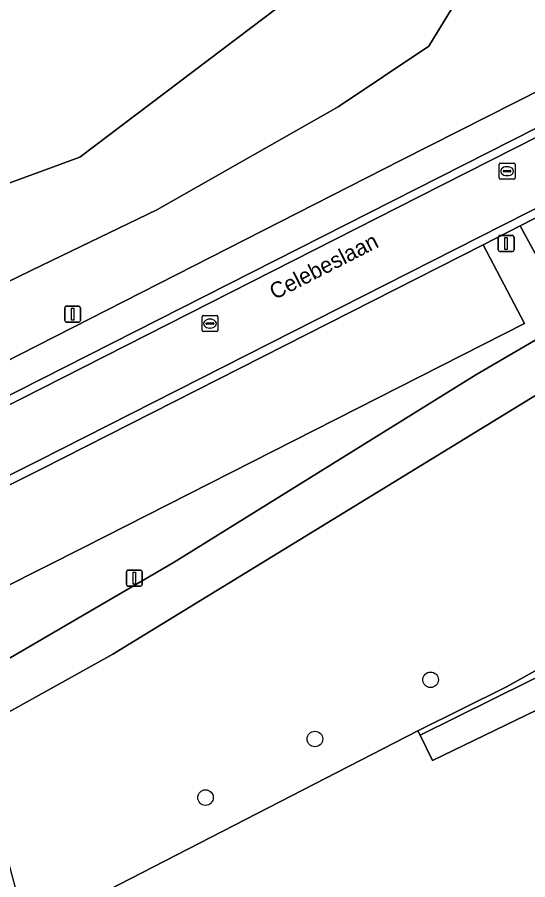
# Model space of a CAD drawing. Extents: x 162879 to 165540, y 384011 to 385181.
# Drawn here: x 163405.9 to 163438, y 384370.1 to 384424.3 of the extents above; entities that cross this region are included whole.
import ezdxf

# ---------------------------------------------------------------- set-up
doc = ezdxf.new("R2010")
doc.units = 0
for name, color, linetype in [('IMGEO_Boom', 7, 'Continuous'), ('IMGEO_Erf', 7, 'Continuous'), ('IMGEO_Grasland_agrarisch', 7, 'Continuous'), ('IMGEO_Groenvoorziening', 7, 'Continuous'), ('IMGEO_Lichtmast', 7, 'Continuous'), ('IMGEO_Loofbos', 7, 'Continuous'), ('IMGEO_Meer_plas_ven_vijver', 7, 'Continuous'), ('IMGEO_Oever', 7, 'Continuous'), ('IMGEO_Openbare_ruimte_label', 7, 'Continuous'), ('IMGEO_Parkeervlak_open', 7, 'Continuous'), ('IMGEO_Rijbaan_lokaal_gesloten', 7, 'Continuous'), ('IMGEO_Rijbaan_lokaal_open', 7, 'Continuous'), ('IMGEO_Rioolput', 7, 'Continuous'), ('IMGEO_Voetpad_open', 7, 'Continuous'), ('IMGEO_Waterloop', 7, 'Continuous')]:
    doc.layers.add(name, color=color, linetype=linetype)

msp = doc.modelspace()

# ---------------------------------------------------------------- linework, layer by layer
at = {"layer": 'IMGEO_Boom'}
for centre in [(163431.908, 384382.643), (163424.634, 384378.918), (163417.752, 384375.234)]:
    msp.add_circle(centre, 0.489, dxfattribs=at)
at = {"layer": 'IMGEO_Erf'}
msp.add_lwpolyline([(163450.353, 384386.442), (163432.033, 384377.572), (163431.249, 384379.155), (163431.11, 384379.435), (163406.542, 384366.796)], dxfattribs=at)
at = {"layer": 'IMGEO_Grasland_agrarisch'}
for points in [[(163373.344, 384387.242), (163392.671, 384396.393), (163404.998, 384402.561), (163430.054, 384415.32), (163455.223, 384428.073)], [(163434.64, 384427.147), (163431.791, 384422.504), (163426.093, 384418.689), (163414.696, 384412.208), (163407.482, 384408.714), (163393.529, 384401.958), (163385.976, 384398.831), (163382.825, 384397.527), (163377.571, 384391.429), (163376.372, 384390.807), (163372.445, 384393.316)]]:
    msp.add_lwpolyline(points, dxfattribs=at)
at = {"layer": 'IMGEO_Groenvoorziening'}
msp.add_lwpolyline([(163434.759, 384401.832), (163440.643, 384405.264), (163440.732, 384405.317), (163437.546, 384411.196), (163435.219, 384410.006), (163437.817, 384405.06), (163410.112, 384390.976), (163399.869, 384385.833), (163399.777, 384385.786), (163401.73, 384381.953), (163402.925, 384382.559), (163415.788, 384390.039)], close=True, dxfattribs=at)
at = {"layer": 'IMGEO_Lichtmast'}
for p, q in [((163436.167, 384409.679), (163436.167, 384410.479)), ((163436.167, 384410.479), (163436.167, 384409.679)), ((163436.267, 384410.579), (163437.057, 384410.579)), ((163437.057, 384410.579), (163436.267, 384410.579)), ((163437.157, 384410.479), (163437.157, 384409.679)), ((163437.157, 384409.679), (163437.157, 384410.479)), ((163437.057, 384409.579), (163436.267, 384409.579)), ((163436.267, 384409.579), (163437.057, 384409.579)), ((163408.893, 384405.238), (163408.893, 384406.038)), ((163408.893, 384406.038), (163408.893, 384405.238)), ((163408.993, 384406.138), (163409.783, 384406.138)), ((163409.783, 384406.138), (163408.993, 384406.138)), ((163409.883, 384406.038), (163409.883, 384405.238)), ((163409.883, 384405.238), (163409.883, 384406.038)), ((163409.783, 384405.138), (163408.993, 384405.138)), ((163408.993, 384405.138), (163409.783, 384405.138)), ((163412.774, 384388.634), (163412.774, 384389.434)), ((163412.774, 384389.434), (163412.774, 384388.634)), ((163412.874, 384389.534), (163413.664, 384389.534)), ((163413.664, 384389.534), (163412.874, 384389.534)), ((163413.764, 384389.434), (163413.764, 384388.634)), ((163413.764, 384388.634), (163413.764, 384389.434)), ((163413.664, 384388.534), (163412.874, 384388.534)), ((163412.874, 384388.534), (163413.664, 384388.534))]:
    msp.add_line(p, q, dxfattribs=at)
for points in [[(163436.587, 384410.454), (163436.737, 384410.454), (163436.737, 384409.704), (163436.587, 384409.704), (163436.587, 384410.454)], [(163409.313, 384406.013), (163409.463, 384406.013), (163409.463, 384405.263), (163409.313, 384405.263), (163409.313, 384406.013)], [(163413.194, 384389.409), (163413.344, 384389.409), (163413.344, 384388.659), (163413.194, 384388.659), (163413.194, 384389.409)]]:
    msp.add_lwpolyline(points, dxfattribs=at)
for centre, start, end in [((163436.267, 384410.479), 90, 180), ((163436.267, 384410.479), 90, 180), ((163437.057, 384410.479), 0, 90), ((163437.057, 384410.479), 360, 90), ((163436.267, 384409.679), 180, 270), ((163436.267, 384409.679), 180, 270), ((163437.057, 384409.679), 270, 0), ((163437.057, 384409.679), 270, 0), ((163408.993, 384406.038), 90, 180), ((163408.993, 384406.038), 90, 180), ((163409.783, 384406.038), 0, 90), ((163409.783, 384406.038), 360, 90), ((163408.993, 384405.238), 180, 270), ((163408.993, 384405.238), 180, 270), ((163409.783, 384405.238), 270, 0), ((163409.783, 384405.238), 270, 0), ((163412.874, 384389.434), 90, 180), ((163412.874, 384389.434), 90, 180), ((163413.664, 384389.434), 0, 90), ((163413.664, 384389.434), 360, 90), ((163412.874, 384388.634), 180, 270), ((163412.874, 384388.634), 180, 270), ((163413.664, 384388.634), 270, 0), ((163413.664, 384388.634), 270, 0)]:
    msp.add_arc(centre, 0.1, start, end, dxfattribs=at)
at = {"layer": 'IMGEO_Loofbos'}
msp.add_lwpolyline([(163431.11, 384379.435), (163436.679, 384382.204), (163448.933, 384389.034), (163448.876, 384389.139), (163449.105, 384389.273), (163449.263, 384389.349), (163442.041, 384402.685), (163411.931, 384384.253), (163403.114, 384379.365), (163406.542, 384366.796)], close=True, dxfattribs=at)
at = {"layer": 'IMGEO_Meer_plas_ven_vijver'}
msp.add_lwpolyline([(163372.906, 384400.903), (163375.7, 384391.868), (163375.807, 384391.922), (163376.372, 384390.807), (163377.571, 384391.429), (163377.047, 384392.564), (163377.156, 384392.615), (163379.868, 384400.144), (163382.737, 384402.812), (163393.452, 384408.404), (163395.885, 384410.398), (163409.847, 384415.517), (163423.24, 384425.652)], dxfattribs=at)
at = {"layer": 'IMGEO_Oever'}
msp.add_lwpolyline([(163423.24, 384425.652), (163409.847, 384415.517), (163395.885, 384410.398), (163393.452, 384408.404), (163382.737, 384402.812), (163379.868, 384400.144), (163377.156, 384392.615), (163377.047, 384392.564), (163377.571, 384391.429), (163382.825, 384397.527), (163385.976, 384398.831), (163393.529, 384401.958), (163407.482, 384408.714), (163414.696, 384412.208), (163426.093, 384418.689), (163431.791, 384422.504), (163434.64, 384427.147)], dxfattribs=at)
msp.add_lwpolyline([(163449.415, 384388.155), (163448.933, 384389.034), (163436.679, 384382.204), (163431.11, 384379.435), (163431.249, 384379.155)], close=True, dxfattribs=at)
at = {"layer": 'IMGEO_Parkeervlak_open'}
for points in [[(163435.219, 384410.006), (163407.444, 384395.905), (163398.254, 384391.345), (163396.481, 384390.495)], [(163397.784, 384390.073), (163399.869, 384385.833), (163410.112, 384390.976), (163437.817, 384405.06), (163435.219, 384410.006)]]:
    msp.add_lwpolyline(points, dxfattribs=at)
at = {"layer": 'IMGEO_Rijbaan_lokaal_gesloten'}
msp.add_lwpolyline([(163397.114, 384391.355), (163398.126, 384391.858), (163407.231, 384396.416), (163434.919, 384410.458), (163456.941, 384421.625), (163471.637, 384429.105), (163469.815, 384432.669), (163456.857, 384426.067), (163431.169, 384413.017), (163406.159, 384400.323), (163393.861, 384394.17), (163393.3, 384393.895), (163383.947, 384389.295), (163378.916, 384387.009), (163374.588, 384385.063)], dxfattribs=at)
at = {"layer": 'IMGEO_Rijbaan_lokaal_open'}
for points in [[(163533.668, 384464.152), (163515.41, 384456.098), (163511.932, 384454.514), (163507.288, 384452.236), (163456.623, 384426.527), (163430.977, 384413.496), (163405.971, 384400.807), (163393.638, 384394.656), (163392.994, 384394.338), (163383.773, 384389.801), (163378.726, 384387.475), (163374.457, 384385.551)], [(163431.169, 384413.017), (163456.857, 384426.067), (163469.815, 384432.669), (163477.728, 384436.724), (163507.529, 384451.791), (163512.124, 384454.058), (163515.616, 384455.639), (163533.887, 384463.696)], [(163531.817, 384458.483), (163524.256, 384455.154), (163514.586, 384450.8), (163513.298, 384450.16), (163511.575, 384449.345), (163501.027, 384444.029), (163479.615, 384433.165), (163479.375, 384433.043), (163471.637, 384429.105), (163456.941, 384421.625), (163434.919, 384410.458), (163407.231, 384396.416), (163398.126, 384391.858), (163397.114, 384391.355), (163394.252, 384389.942)], [(163394.976, 384389.721), (163396.481, 384390.495), (163398.254, 384391.345), (163407.444, 384395.905), (163435.219, 384410.006), (163437.546, 384411.196), (163439.174, 384412.039), (163439.373, 384412.14), (163450.384, 384417.731), (163450.879, 384417.982), (163457.107, 384421.146), (163462.473, 384423.873), (163479.686, 384432.623), (163501.208, 384443.552), (163511.836, 384448.897), (163513.512, 384449.702), (163514.861, 384450.369), (163524.505, 384454.716), (163532.023, 384458.022)], [(163374.588, 384385.063), (163378.916, 384387.009), (163383.947, 384389.295), (163393.3, 384393.895), (163393.861, 384394.17), (163406.159, 384400.323), (163431.169, 384413.017)]]:
    msp.add_lwpolyline(points, dxfattribs=at)
at = {"layer": 'IMGEO_Rioolput'}
for p, q in [((163436.224, 384414.206), (163436.224, 384415.058)), ((163436.299, 384415.132), (163437.151, 384415.132)), ((163437.225, 384415.058), (163437.225, 384414.206)), ((163436.483, 384414.626), (163436.483, 384414.638)), ((163436.921, 384414.589), (163436.523, 384414.589)), ((163436.526, 384414.675), (163436.924, 384414.675)), ((163436.712, 384414.912), (163436.737, 384414.912)), ((163436.967, 384414.638), (163436.967, 384414.626)), ((163437.151, 384414.132), (163436.299, 384414.132)), ((163436.735, 384414.352), (163436.71, 384414.352)), ((163417.53, 384404.621), (163417.53, 384405.473)), ((163417.605, 384405.547), (163418.457, 384405.547)), ((163418.018, 384405.327), (163418.043, 384405.327)), ((163418.531, 384405.473), (163418.531, 384404.621)), ((163417.789, 384405.041), (163417.789, 384405.053)), ((163418.227, 384405.004), (163417.829, 384405.004)), ((163417.832, 384405.09), (163418.23, 384405.09)), ((163418.041, 384404.767), (163418.016, 384404.767)), ((163418.273, 384405.053), (163418.273, 384405.041)), ((163418.457, 384404.547), (163417.605, 384404.547))]:
    msp.add_line(p, q, dxfattribs=at)
for points in [[(163436.224, 384414.206), (163436.224, 384415.058)], [(163436.299, 384415.132), (163437.151, 384415.132)], [(163437.225, 384415.058), (163437.225, 384414.206)], [(163437.151, 384414.132), (163436.299, 384414.132)], [(163417.53, 384404.621), (163417.53, 384405.473)], [(163417.605, 384405.547), (163418.457, 384405.547)], [(163418.531, 384405.473), (163418.531, 384404.621)], [(163418.457, 384404.547), (163417.605, 384404.547)]]:
    msp.add_lwpolyline(points, dxfattribs=at)
for centre, radius, start, end in [((163436.301, 384415.056), 0.0765, 91.552, 178.448), ((163436.301, 384415.056), 0.0765, 91.552, 178.448), ((163437.149, 384415.056), 0.0765, 1.552, 88.448), ((163437.149, 384415.056), 0.0765, 1.552, 88.448), ((163436.523, 384414.635), 0.0403, 85.8775, 175.7526), ((163436.52, 384414.625), 0.0366, 178.938, 274.7102), ((163436.924, 384414.632), 0.043, 264.8664, 352.4533), ((163436.928, 384414.637), 0.0386, 1.7309, 96.639), ((163436.301, 384414.208), 0.0765, 181.552, 268.448), ((163436.301, 384414.208), 0.0765, 181.552, 268.448), ((163437.149, 384414.208), 0.0765, 271.552, 358.448), ((163437.149, 384414.208), 0.0765, 271.552, 358.448), ((163417.607, 384405.471), 0.0765, 91.552, 178.448), ((163417.607, 384405.471), 0.0765, 91.552, 178.448), ((163418.455, 384405.471), 0.0765, 1.552, 88.448), ((163418.455, 384405.471), 0.0765, 1.552, 88.448), ((163417.607, 384404.623), 0.0765, 181.552, 268.448), ((163417.607, 384404.623), 0.0765, 181.552, 268.448), ((163417.829, 384405.05), 0.0403, 85.8775, 175.7526), ((163417.826, 384405.04), 0.0366, 178.938, 274.7102), ((163418.23, 384405.047), 0.043, 264.8664, 352.4533), ((163418.234, 384405.052), 0.0386, 1.7309, 96.639), ((163418.455, 384404.623), 0.0765, 271.552, 358.448), ((163418.455, 384404.623), 0.0765, 271.552, 358.448)]:
    msp.add_arc(centre, radius, start, end, dxfattribs=at)
for centre, major_axis, ratio, start_param, end_param in [((163436.711, 384414.632), (-0.387, 0.002), 0.722429, 4.712389, 7.853982), ((163436.736, 384414.632), (-0.39, 0.002), 0.717154, 1.570796, 4.712389), ((163418.017, 384405.047), (-0.387, 0.002), 0.722429, 4.712389, 7.853982), ((163418.042, 384405.047), (-0.39, 0.002), 0.717154, 1.570796, 4.712389)]:
    msp.add_ellipse(centre, major_axis=major_axis, ratio=ratio, start_param=start_param, end_param=end_param, dxfattribs=at)
at = {"layer": 'IMGEO_Voetpad_open'}
for points in [[(163538.679, 384466.281), (163537.834, 384468.229), (163524.589, 384462.42), (163519.897, 384460.317), (163514.547, 384458.003), (163510.842, 384456.216), (163506.36, 384454.019), (163455.744, 384428.337), (163455.223, 384428.073), (163430.054, 384415.32), (163404.998, 384402.561), (163392.671, 384396.393), (163373.344, 384387.242)], [(163374.457, 384385.551), (163378.726, 384387.475), (163383.773, 384389.801), (163392.994, 384394.338), (163393.638, 384394.656), (163405.971, 384400.807), (163430.977, 384413.496), (163456.623, 384426.527), (163507.288, 384452.236), (163511.932, 384454.514), (163515.41, 384456.098), (163533.668, 384464.152)], [(163439.174, 384412.039), (163437.546, 384411.196), (163440.732, 384405.317)], [(163440.643, 384405.264), (163434.759, 384401.832), (163415.788, 384390.039), (163402.925, 384382.559), (163401.73, 384381.953), (163400.103, 384381.128), (163391.789, 384376.91), (163380.931, 384371.875), (163380.358, 384371.609), (163378.478, 384370.737), (163361.047, 384363.344)], [(163381.796, 384369.032), (163387.559, 384371.642), (163400.878, 384378.126), (163401.499, 384378.47), (163403.114, 384379.365), (163411.931, 384384.253), (163442.041, 384402.685)]]:
    msp.add_lwpolyline(points, dxfattribs=at)
at = {"layer": 'IMGEO_Waterloop'}
msp.add_lwpolyline([(163450.353, 384386.442), (163449.415, 384388.155), (163431.249, 384379.155), (163432.033, 384377.572)], close=True, dxfattribs=at)

# ---------------------------------------------------------------- texts
at = {"layer": 'IMGEO_Openbare_ruimte_label'}
msp.add_text('Celebeslaan', height=1, rotation=27.0007, dxfattribs=at).set_placement((163422.101, 384406.524))

doc.saveas('drawing.dxf')
